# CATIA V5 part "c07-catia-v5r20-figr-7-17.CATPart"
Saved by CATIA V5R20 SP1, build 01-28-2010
Part number: Part2
Bounding box of the stored display mesh (mm): x -50 to 50, y -65 to 65, z 0 to 28
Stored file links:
  D:\v5_r20\psrt_files_downloaded\c07-catia-v5r20-prt\c07-catia-v5r20-figr-7-17.CATPart
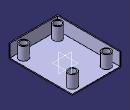
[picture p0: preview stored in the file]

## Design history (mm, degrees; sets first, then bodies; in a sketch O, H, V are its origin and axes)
Body1 (main body)
  Sketch1 on xy-plane, origin (0, 0, 0), H (1, 0, 0), V (0, 1, 0)
    line L1 (-50, 65) -> (50, 65)
    line L2 (50, 65) -> (50, -65)
    line L3 (50, -65) -> (-50, -65)
    line L4 (-50, -65) -> (-50, 65)
    axis line L5 (50, -65) -> (-50, 65)
    length L3 = 100
    length L2 = 130
    horizontal: L1 H, L3 H
    vertical: L2 V, L4 V
    midpoint: O L5
  Pad1: profile Sketch1, direction (0, 0, 1), length 28
  Sketch2 on face of Pad1, origin (25.9302, -33.7092, 28), H (1, 0, 0), V (0, 1, 0)
    point P1 (9.0698, -16.2908)
    reference projected line E1 (-75.9302, -31.2908) -> (24.0698, -31.2908) from edge [face of Pad1 | face of Pad1]
    reference projected line E2 (24.0698, -31.2908) -> (24.0698, 98.7092) from edge [face of Pad1 | face of Pad1]
    distance P1 E1 = 15
    distance P1 E2 = 15
  Hole1: placed by Sketch2, at (35, -50, 28) direction (0, 0, -1), diameter 14, through (limit type 3)
  RectPattern1: of Hole1, direction 1 instances 2, spacing 100, along edge [face of Pad1 | face of Pad1], direction 2 instances 2, spacing 70, along edge [face of Pad1 | face of Pad1]
  Shell1: IntOffset 2, Face (face of Pad1; face of Pad1; face of Pad1), ExtOffset 0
